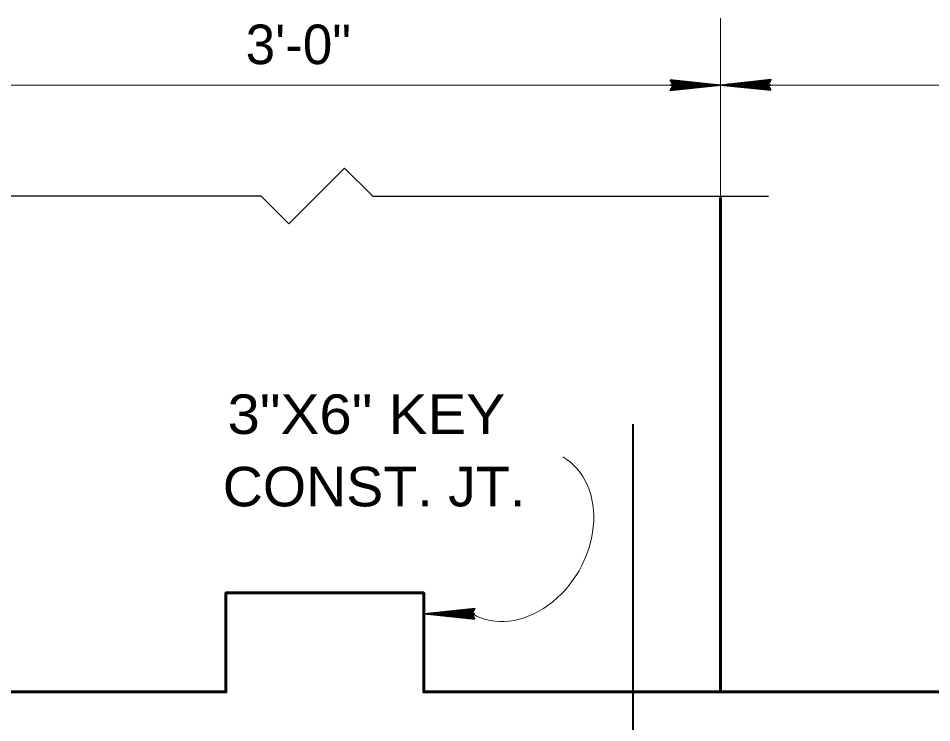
# Model space of a CAD drawing. Extents: x 14.14 to 17.34, y -1.61 to 0.38.
# Drawn here: x 16.1851 to 16.3775, y 0.0616 to 0.21 of the extents above; entities that cross this region are included whole.
import ezdxf

# ---------------------------------------------------------------- set-up
doc = ezdxf.new("R2010")
doc.units = 0
doc.header["$LTSCALE"] = 0.0033
doc.layers.add('1', color=7, linetype='Continuous', lineweight=40)

msp = doc.modelspace()

# ---------------------------------------------------------------- linework, layer by layer
at = {"layer": '1', "lineweight": 13}
for p, q in [((16.333, 0.17225), (16.333, 0.21)), ((16.000417, 0.195917), (16.499083, 0.195917))]:
    msp.add_line(p, q, dxfattribs=at)
at = {"layer": '1', "lineweight": 35}
for p, q in [((16.322667, 0.196917), (16.3305, 0.196)), ((16.322667, 0.196917), (16.3305, 0.196)), ((16.322667, 0.196833), (16.3305, 0.196)), ((16.322667, 0.19675), (16.3305, 0.195917)), ((16.322667, 0.19675), (16.3305, 0.19575)), ((16.343333, 0.197), (16.336, 0.196167)), ((16.343333, 0.196833), (16.336, 0.196083)), ((16.343333, 0.19675), (16.336, 0.195917)), ((16.343417, 0.196583), (16.336083, 0.195833)), ((16.322417, 0.195917), (16.333, 0.195917)), ((16.322583, 0.19525), (16.329917, 0.196)), ((16.322667, 0.195083), (16.33, 0.195917)), ((16.322667, 0.195), (16.33, 0.19575)), ((16.322667, 0.194833), (16.33, 0.195667)), ((16.343583, 0.195917), (16.333, 0.195917)), ((16.343333, 0.195083), (16.3355, 0.196083)), ((16.343333, 0.195083), (16.3355, 0.195917)), ((16.343333, 0.194917), (16.3355, 0.195833)), ((16.343333, 0.194917), (16.3355, 0.195833)), ((16.343333, 0.195), (16.3355, 0.195833)), ((16.281, 0.083667), (16.273167, 0.084667)), ((16.281, 0.085583), (16.273667, 0.08475)), ((16.281, 0.085417), (16.273667, 0.084667)), ((16.281, 0.085333), (16.273667, 0.0845)), ((16.281083, 0.085167), (16.27375, 0.084417)), ((16.28125, 0.0845), (16.270667, 0.0845)), ((16.281, 0.083667), (16.273167, 0.0845)), ((16.281, 0.0835), (16.273167, 0.084417)), ((16.281, 0.0835), (16.273167, 0.084417)), ((16.281, 0.083583), (16.273167, 0.084417))]:
    msp.add_line(p, q, dxfattribs=at)
for points in [[(16.322417, 0.197), (16.333, 0.195917), (16.322417, 0.19475), (16.323, 0.195917)], [(16.323167, 0.196), (16.327833, 0.196083), (16.327833, 0.196), (16.326917, 0.196), (16.323167, 0.196083), (16.326167, 0.196167), (16.323, 0.19625), (16.32525, 0.196333), (16.323, 0.196417), (16.3265, 0.196167), (16.331167, 0.196), (16.33025, 0.19575), (16.3315, 0.19575), (16.323167, 0.19575), (16.325583, 0.195583), (16.323, 0.195583), (16.328333, 0.196), (16.323, 0.195333)], [(16.343583, 0.194833), (16.333, 0.195917), (16.343583, 0.197083), (16.343, 0.195917)], [(16.342833, 0.195833), (16.338167, 0.19575), (16.338167, 0.195833), (16.339083, 0.195833), (16.342833, 0.19575), (16.339833, 0.195667), (16.343, 0.195583), (16.34075, 0.1955), (16.343, 0.195417), (16.3395, 0.195667), (16.334833, 0.195833), (16.33575, 0.196083), (16.3345, 0.196083), (16.342833, 0.196083), (16.340417, 0.19625), (16.343, 0.19625), (16.337667, 0.195833), (16.343, 0.1965)], [(16.28125, 0.083417), (16.270667, 0.0845), (16.28125, 0.085667), (16.280667, 0.0845)], [(16.2805, 0.084417), (16.275833, 0.084333), (16.275833, 0.084417), (16.27675, 0.084417), (16.2805, 0.084333), (16.2775, 0.08425), (16.280667, 0.084167), (16.278417, 0.084083), (16.280667, 0.084), (16.277167, 0.08425), (16.2725, 0.084417), (16.273417, 0.084667), (16.272167, 0.084667), (16.2805, 0.084667), (16.278083, 0.084833), (16.280667, 0.084833), (16.275333, 0.084417), (16.280667, 0.085083)]]:
    msp.add_lwpolyline(points, close=True, dxfattribs=at)
for points in [[(16.323167, 0.196), (16.32275, 0.19675), (16.323, 0.1965), (16.323167, 0.196167), (16.323417, 0.19625), (16.32325, 0.196583), (16.323083, 0.195833), (16.322917, 0.195333), (16.322667, 0.194917)], [(16.342833, 0.195833), (16.34325, 0.195083), (16.343, 0.195333), (16.342833, 0.195667), (16.342583, 0.195583), (16.34275, 0.19525), (16.342917, 0.196), (16.343083, 0.1965), (16.343333, 0.196917)], [(16.2805, 0.084417), (16.280917, 0.083667), (16.280667, 0.083917), (16.2805, 0.08425), (16.28025, 0.084167), (16.280417, 0.083833), (16.280583, 0.084583), (16.28075, 0.085083), (16.281, 0.0855)]]:
    msp.add_lwpolyline(points, dxfattribs=at)
at = {"layer": '1', "lineweight": 25}
msp.add_lwpolyline([(16.152833, 0.172583), (16.236167, 0.172583), (16.242083, 0.166667), (16.253833, 0.178417), (16.25975, 0.1725), (16.343083, 0.1725)], dxfattribs=at)
at = {"layer": '1', "lineweight": 60}
for points in [[(16.333, 0.17225), (16.333, 0.068083), (16.499667, 0.068083)], [(16.166333, 0.068083), (16.228833, 0.068083), (16.228833, 0.088917), (16.2705, 0.088917), (16.2705, 0.068083), (16.333, 0.068083)]]:
    msp.add_lwpolyline(points, dxfattribs=at)
at = {"layer": '1'}
msp.add_lwpolyline([(16.3145, 0.1245), (16.3145, 0.0115), (16.377, 0.0115)], dxfattribs=at)
at = {"layer": '1', "lineweight": 13}
msp.add_ellipse((16.29025, 0.101042), major_axis=(-0.0095, -0.016542), ratio=0.782092, start_param=6.2831853, end_param=9.424778, dxfattribs=at)

# ---------------------------------------------------------------- texts
at = {"layer": '1'}
msp.add_text('3\'-0"', height=0.008333, dxfattribs=at).set_placement((16.233, 0.200333))
for s, width, p in [('3"X6" KEY', 1.1, (16.229167, 0.122417)), ('CONST. JT. ', 1.05, (16.228167, 0.107167))]:
    msp.add_text(s, height=0.008334, dxfattribs=dict(at, width=width)).set_placement(p)

doc.saveas('drawing.dxf')
